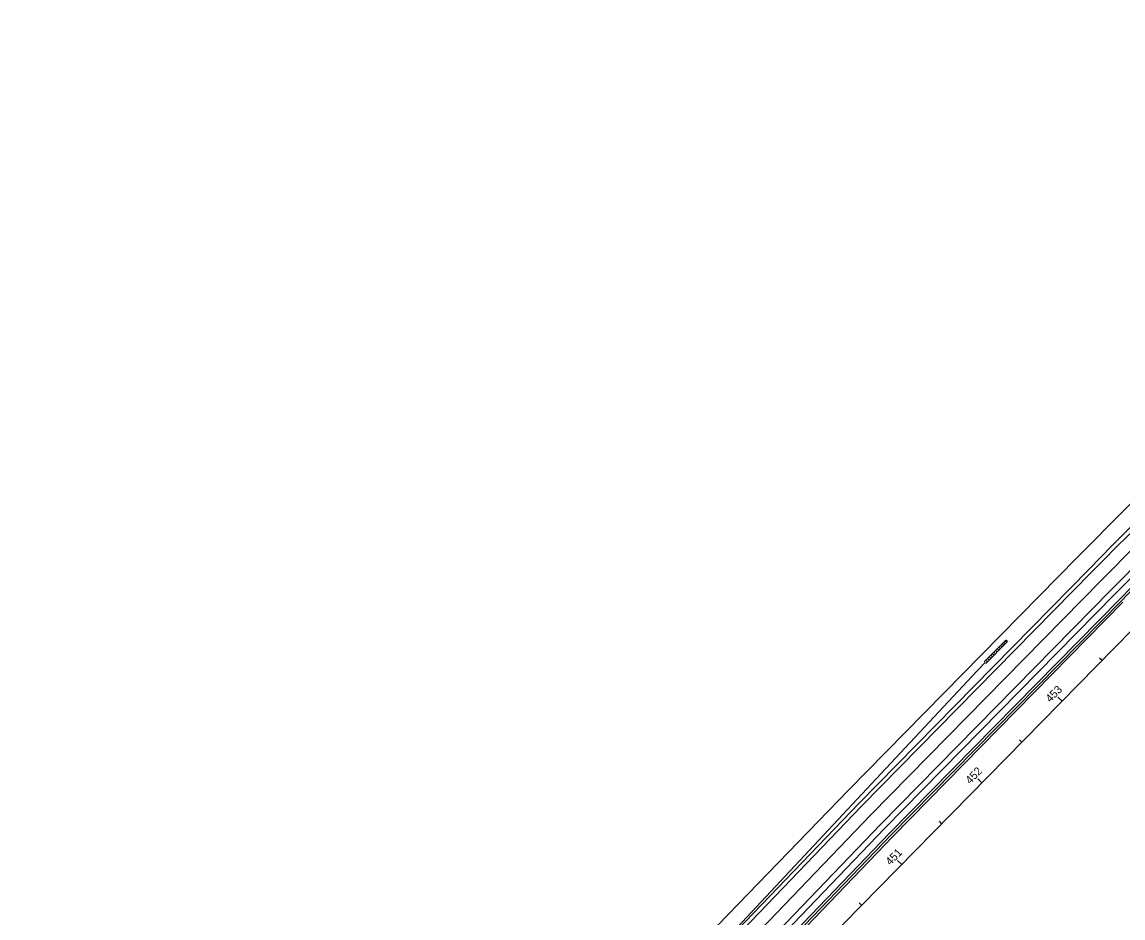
# Model space of a CAD drawing. Extents: x 142554 to 147512, y 370190 to 373751.
# Drawn here: x 144390 to 145352, y 371853 to 372636 of the extents above; entities that cross this region are included whole.
import ezdxf

# ---------------------------------------------------------------- set-up
doc = ezdxf.new("R2010")
doc.units = 0
for name, color, linetype in [('DR_P_Cells', 7, 'Continuous'), ('DR_P_Storm_Sewer', 7, 'Continuous'), ('DR_X_Cells', 7, 'Continuous'), ('DR_X_GenericNode', 7, 'Continuous'), ('FeatureService_Stream Network', 7, 'Continuous'), ('FeatureService_Water Bodies', 7, 'Continuous'), ('PF_X_Ground_Line', 7, 'Continuous'), ('PM_X_Edge_Line', 7, 'Continuous'), ('RD_X_GR_Cable_Bar', 7, 'Continuous'), ('SC_Scratch20', 7, 'Continuous')]:
    doc.layers.add(name, color=color, linetype=linetype)

msp = doc.modelspace()

# ---------------------------------------------------------------- linework, layer by layer
at = {"layer": 'DR_P_Cells'}
for points in [[(144375.11, 371179.46), (144652.68, 371450.31), (144919.03, 371721.55), (144931.96, 371734.79), (145131.57, 371942.86), (145332.92, 372147.7)], [(144383.56, 371170.93), (144661.15, 371441.81), (144927.61, 371713.15), (144940.58, 371726.45), (145140.18, 371934.5), (145341.48, 372139.29)]]:
    msp.add_lwpolyline(points, dxfattribs=at)
for radius in [5722, 5710]:
    msp.add_arc((149413.6, 368136.55), radius, 130.71653, 135.49226, dxfattribs=at)
at = {"layer": 'DR_P_Storm_Sewer'}
for p, q in [((145249.15, 372095.15), (145230.86, 372076.67)), ((145250.57, 372093.74), (145232.28, 372075.26)), ((145240.7, 372086.61), (145242.12, 372085.2)), ((145242.11, 372088.03), (145243.53, 372086.62)), ((145243.51, 372089.45), (145244.93, 372088.04)), ((145244.92, 372090.87), (145246.34, 372089.47)), ((145246.33, 372092.29), (145247.75, 372090.89)), ((145247.73, 372093.72), (145249.15, 372092.31)), ((145249.14, 372095.14), (145250.56, 372093.73)), ((145232.26, 372078.08), (145233.68, 372076.67)), ((145233.66, 372079.5), (145235.08, 372078.1)), ((145235.07, 372080.92), (145236.49, 372079.52)), ((145236.48, 372082.34), (145237.9, 372080.94)), ((145237.88, 372083.77), (145239.31, 372082.36)), ((145239.29, 372085.19), (145240.71, 372083.78))]:
    msp.add_line(p, q, dxfattribs=at)
msp.add_arc((145249.86, 372094.44), 1, 315.74249, 135.74249, dxfattribs=at)
at = {"layer": 'DR_X_Cells'}
for p, q in [((145224.54, 372068.86), (145231.57, 372075.97)), ((144908.94, 371731.25), (145224.54, 372068.86))]:
    msp.add_line(p, q, dxfattribs=at)
at = {"layer": 'DR_X_GenericNode'}
for points in [[(144342.37, 371162.87), (144644.83, 371458.02), (144911.08, 371729.15), (144923.95, 371742.35), (145123.58, 371950.42), (145324.99, 372155.32)], [(144416.12, 371187.34), (144668.82, 371433.92), (144935.38, 371705.37), (144948.4, 371718.72), (145147.98, 371926.75), (145349.23, 372131.49)]]:
    msp.add_lwpolyline(points, dxfattribs=at)
for centre, radius, end in [((149414.22, 368135.75), 5734, 135.492256), ((149412.8, 368137.16), 5698, 135.49226)]:
    msp.add_arc(centre, radius, 130.71653, end, dxfattribs=at)
at = {"layer": 'FeatureService_Stream Network'}
msp.add_lwpolyline([(145322.49, 372157.77), (145121.08, 371952.87), (144908.69, 371731.49)], dxfattribs=at)
msp.add_arc((149412.8, 368137.16), 5735.5, 130.883952, 135.492256, dxfattribs=at)
at = {"layer": 'FeatureService_Water Bodies'}
for points in [[(145352.09, 372128.68), (145150.85, 371923.96), (144951.28, 371715.94), (144938.24, 371702.57), (144671.65, 371431.09), (144394.01, 371160.17)], [(145352.09, 372128.68), (145150.85, 371923.96), (144951.28, 371715.94), (144938.24, 371702.57), (144671.65, 371431.09), (144394.01, 371160.17)], [(144492.32, 371258.89), (144670.24, 371432.5), (144936.81, 371703.97), (144949.84, 371717.33), (145149.42, 371925.35), (145350.66, 372130.08)], [(144492.32, 371258.89), (144670.24, 371432.5), (144936.81, 371703.97), (144949.84, 371717.33), (145149.42, 371925.35), (145350.66, 372130.08)]]:
    msp.add_lwpolyline(points, dxfattribs=at)
msp.add_arc((149412.8, 368137.16), 5696, 130.71653, 135.49226, dxfattribs=at)
msp.add_arc((149412.8, 368137.16), 5696, 130.71653, 135.49226, dxfattribs=at)
at = {"layer": 'PF_X_Ground_Line'}
for points in [[(144391.17, 371162.99), (144591.67, 371364.33), (144944.19, 371723), (145143.68, 371930.93), (145344.96, 372135.69)], [(145350.66, 372130.08), (145149.42, 371925.35), (144949.84, 371717.33), (144936.81, 371703.97), (144670.24, 371432.5), (144492.32, 371258.89)]]:
    msp.add_lwpolyline(points, dxfattribs=at)
for radius, start in [(5704, 128.88811), (5696, 130.71653)]:
    msp.add_arc((149412.8, 368137.16), radius, start, 135.49226, dxfattribs=at)
at = {"layer": 'PM_X_Edge_Line'}
msp.add_line((144376.23, 371102.81), (145360.57, 372105.07), dxfattribs=at)
at = {"layer": 'RD_X_GR_Cable_Bar'}
for p, q in [((145333.83, 372077.84), (145331.69, 372079.95)), ((145298.8, 372042.17), (145295.23, 372045.67)), ((145263.76, 372006.5), (145261.62, 372008.6)), ((145228.73, 371970.83), (145225.16, 371974.33)), ((145193.69, 371935.15), (145191.55, 371937.25)), ((145158.66, 371899.48), (145155.09, 371902.98)), ((145123.62, 371863.81), (145121.48, 371865.91))]:
    msp.add_line(p, q, dxfattribs=at)
at = {"layer": 'SC_Scratch20'}
msp.add_lwpolyline([(144176.13, 371012.23), (144556.99, 371396.08), (144910.51, 371755.96), (145111.72, 371964.03), (145312.15, 372167.94)], dxfattribs=at)
msp.add_arc((149412.8, 368137.16), 5750, 122.730831, 135.492256, dxfattribs=at)

# ---------------------------------------------------------------- texts
at = {"layer": 'RD_X_GR_Cable_Bar'}
for s, p in [('453', (145288.6, 372040.71)), ('452', (145218.52, 371969.35)), ('451', (145148.68, 371898.24))]:
    msp.add_text(s, height=7, rotation=45.5169, dxfattribs=at).set_placement(p)

doc.saveas('drawing.dxf')
